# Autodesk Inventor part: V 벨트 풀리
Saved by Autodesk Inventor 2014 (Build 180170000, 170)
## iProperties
Created: 2025-10
Part Number: V 벨트 풀리
Material: 일반
Document SubType Name: Modeling
Designer: dg
Density: 1 g/cm^3
Appearance: 기본값
Author: dg
Author: jhkim
Creation Date: 2025-10-01
Sending System: Autodesk Inventor 2026
Preprocessor: ST-DEVELOPER v20.1
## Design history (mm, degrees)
node "V 벨트 풀리1"
node "솔리드1"
node "기준1"
